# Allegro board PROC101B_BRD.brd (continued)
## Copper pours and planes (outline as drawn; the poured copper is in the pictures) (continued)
DGND on BOTTOM (solid shape): 53.45,39.36 53.54,39.31 53.54,39.22 53.52,38.81 53.8,38.51 53.86,38.43 53.83,38.35 53.77,38.26 53.72,38.16 53.64,38.09 53.54,38.14 52.81,38.32 52.63,37.58 52.63,37.53 52.59,37.5 52.48,37.5 52.47,37.55 51.76,37.75 52.06,37.07 52.09,37.07 52.14,37.02 52.1,36.97 52.09,36.97 51.85,36.36 52.49,36.3 52.83,36.3 53.04,36.1 53.04,35.37 51.92,35.37 51.92,35.34 51.86,35.34 51.5,35.2 51.43,34.82 51.41,34.73 51.33,34.69 51.25,34.69 51.23,34.7 50.99,34.82 50.73,34.75 50.62,34.75 50.57,34.84 50.57,36.72 53.22,39.36
DGND on BOTTOM (solid shape): outline of 82 points within 82.24,50.35 89.12,63.35
DGND on BOTTOM (solid shape): outline of 208 points within 36.22,114.53 44.73,125.41
DGND on BOTTOM (solid shape): outline of 202 points within 76.78,67.46 83.73,72.29
DGND on BOTTOM (solid shape): 18.78,33.55 18.87,33.5 19.27,33.07 19.85,32.94 19.93,32.91 19.96,32.83 19.95,32.7 19.96,32.57 19.93,32.49 19.85,32.46 19.27,32.33 18.87,31.9 18.78,31.85 18.69,31.9 17.05,32.16 17.35,30.53 17.41,30.44 17.45,30.35 17.47,30.32 17.47,30.25 17.4,30.25 16.55,30.44 15.87,29.9 15.78,29.85 15.69,29.9 15.33,30.3 14.82,30.47 14.73,30.53 14.75,30.64 15.04,30.93 15.04,32.19 15.23,32.38 15.58,32.38 15.9,32.69 15.91,32.69 16.02,32.76 16.1,32.85 16.14,32.94 16.2,33.03 16.48,33.22 16.69,33.5 16.78,33.55 17.78,32.93
DGND on BOTTOM (solid shape): 29.83,89.66 32.68,89.66 34.14,88.2 35.14,88.2 35.27,88.11 35.43,88.08 35.45,88.07 35.51,88.01 35.51,87.62 34.79,87.62 34.28,87.69 34.12,87.2 34.11,87.11 34.02,87.06 31.62,87.06 31.54,87.1 31.52,87.18 31.11,87.66 30.71,87.18 30.69,87.1 30.61,87.06 26.83,87.06 25.36,88.53 25.33,88.64 25.42,88.71 25.59,88.75 25.72,88.85 25.83,88.88 25.9,88.79 25.9,88.2 27.06,88.2 27.06,89.47 28.07,89.47 28.07,89.59 28.09,89.66 28.17,89.69 28.56,90.1 28.17,90.5 28.09,90.53 28.07,90.6 28.07,90.72 25.92,90.72 25.92,90.37 25.66,90.37 25,90.01 25.73,89.82 25.92,89.82 25.92,89.45 25.9,89.45 25.9,89.44 25.83,89.34 25.72,89.37 25.28,89.5 25,89.13 24.93,89.04 24.82,89.06 23.1,90.79 23.08,90.9 23.17,90.96 28.54,90.96
DGND on BOTTOM (solid shape): 129.87,24.76 129.95,24.72 129.97,24.63 129.96,24.58 129.96,24.53 129.93,24.46 129.85,24.43 129.73,24.43 129.73,22.55 129.85,22.55 129.93,22.52 129.96,22.45 130.36,22.04 130.77,22.45 130.8,22.52 130.87,22.55 131,22.55 131,23.21 131.22,23.21 131.3,23.14 131.3,21.08 130.42,20.21 127.95,20.21 126.56,18.82 125.72,18.82 125.72,19.12 124.47,19.12 124.47,18.82 124.19,18.82 124.19,19.12 122.95,19.12 122.95,18.82 122.68,18.82 122.63,18.77 122.58,18.8 122.42,18.8 122.33,18.85 122.33,18.95 122.34,19.31 122.06,19.54 121.98,19.61 122.01,19.71 124.26,21.96 124.28,21.96 124.65,22.23 124.54,22.67 124.51,22.79 124.61,22.85 125.78,22.85 125.88,22.79 125.86,22.69 126.17,22.02 126.48,22.69 126.47,22.79 126.56,22.85 127.34,22.85 127.51,22.74 127.71,22.73 127.79,22.71 127.83,22.63 127.83,22.55 127.95,22.55 128.03,22.52 128.06,22.45 128.46,22.04 128.87,22.45 128.9,22.52 128.97,22.55 129.1,22.55 129.1,24.25 129.27,24.25 129.78,24.76
DGND on BOTTOM (solid shape): 137.3,54.31 137.36,54.41 137.48,54.37 137.73,54.22 138.02,54.29 138.03,54.29 138.12,54.29 138.12,54 139.1,54 139.1,52.73 139.17,52.73 139.25,52.7 139.28,52.63 139.3,52.48 139.37,52.35 139.39,52.26 139.32,52.19 139.08,51.68 139.58,51.42 139.67,51.41 139.71,51.33 139.71,51.23 140.96,51.23 140.96,52.4 140.89,52.4 140.84,52.43 140.85,52.48 140.99,52.62 141.76,52.62 141.76,51.42 141.89,51.42 141.89,50.09 141.67,49.87 141.64,49.89 141.26,49.86 141.06,49.54 141.03,49.47 140.96,49.44 139.74,49.44 139.64,49.51 139.68,49.62 139.81,50.08 139.41,50.35 139.34,50.38 139.31,50.45 139.31,50.53 138.06,50.53 138.06,50.3 138,50.2 137.89,50.22 137.78,50.33 137.01,50.33 136.93,50.37 136.91,50.46 136.93,50.56 136.92,50.67 136.94,50.75 137.02,50.79 137.44,51.19 137.04,51.6 137.02,51.6 136.99,51.63 136.79,51.63 136.79,51.76 135.57,51.76 135.57,51.37 135.19,51.37 135.19,52.55 135.57,52.55 135.57,52.15 136.79,52.15 136.79,52.28 136.86,52.28 137.17,52.59 137.18,52.59 137.44,52.93 137.25,53.32 137.21,53.39 137.24,53.47 137.3,53.53
DGND on BOTTOM (solid shape): 45.03,120.02 47.81,120.02 47.81,119.42 47.78,119.35 47.71,119.32 47.34,118.91 47.71,118.51 47.78,118.48 47.81,118.41 47.81,117.52 47.78,117.45 47.71,117.41 47.34,117.01 47.71,116.6 47.78,116.57 47.81,116.5 47.81,115.87 50.12,115.87 50.12,116.12 54.4,116.12 54.6,116.32 54.81,116.32 54.89,116.27 54.89,116.17 55.24,115.56 55.6,116.17 55.6,116.27 55.68,116.32 55.89,116.32 56.37,115.85 56.39,115.76 56.34,115.69 56.33,114.98 56.94,115.33 56.97,115.41 57.04,115.44 59.36,115.44 59.45,115.37 59.42,115.26 59.3,115.07 59.3,114.85 59.28,114.76 59.2,114.72 58.05,114.72 57.29,113.96 56.97,113.96 56.89,114.01 56.89,114.11 56.54,114.72 56.18,114.11 56.18,114.01 56.1,113.96 55.61,113.96 54.47,115.1 46.25,115.1 45.06,116.29 45.06,117.6 44.68,117.98 44.12,117.98 44.12,118.33 44.17,118.41 44.27,118.42 44.84,118.7 44.45,119.19 44.43,119.19 44.34,119.28 44.12,119.28 44.12,119.9 44.17,119.99 44.27,119.99 44.52,119.96 44.75,120.08 44.97,120.08
DGND on BOTTOM (solid shape): outline of 90 points within 93.22,85.82 95.3,100.3
DGND on BOTTOM (solid shape): outline of 321 points within 67.53,35.26 88.08,43.75
DGND on BOTTOM (solid shape): outline of 308 points within 98.19,76.44 102.85,81.9
DGND on BOTTOM (solid shape): outline of 384 points within 91.52,67.84 94,73.66
DGND on BOTTOM (solid shape): outline of 98 points within 78.02,38.24 94.39,56.69
DGND on BOTTOM (solid shape): outline of 403 points within 94.15,70.68 100.35,73.99
DGND on BOTTOM (solid shape): outline of 412 points within 97.56,82.16 100.22,86.04
DGND on BOTTOM (solid shape): outline of 147 points within 69.09,63.03 75.49,74.32
DGND on BOTTOM (solid shape): outline of 126 points within 111.69,64.81 120.65,89.79
DGND on BOTTOM (solid shape): outline of 755 points within 85.34,66.15 89.71,74.18
DGND on BOTTOM (solid shape): outline of 855 points within 36.22,86.57 51.24,106.22
DGND on BOTTOM (solid shape): outline of 2692 points within 41.16,56.74 73.34,87.79
DGND on BOTTOM (solid shape): outline of 9214 points within 1.02,87.56 89.97,132.98
DGND on BOTTOM (solid shape): outline of 50199 points within 1.02,8.02 176.78,132.98
DGND on TOP: 140.61,88.7 140.61,132.97 176.78,132.97 176.78,88.7 171.09,88.7 170.99,88.6 170.99,81.1 167.06,81.1 167.06,78.1 165.84,76.88 164.29,76.88 164.29,84.38 157.89,84.38 157.89,76.88 155.56,76.88 154.81,77.62 154.81,81.14 151.23,81.14 151.23,77.44 150.16,76.38 146.96,76.38 146.96,88.49 146.76,88.7
DGND on TOP: 97.33,63.96 97.33,54.79 125.6,54.79 125.6,63.96 ; 5 cut-outs
DGND on TOP: 130.63,49.12 130.63,70.41 148.13,70.41 148.13,61.21 143.33,56.41 137.92,56.41 ; 1 cut-out
DGND on TOP: 106.86,33.1 115.32,33.1 115.24,33.17 115.24,40.72 112.6,43.36 112.6,46.81 111.81,46.81 109.07,44.07 109.07,38.79 106.53,36.25 106.53,33.43
DGND on TOP: 63.12,33.68 63.12,44.75 76.25,44.75 76.35,44.86 76.35,46.2 85.55,46.2 86.03,45.72 86.03,44.75 86.28,44.75 86.28,33.68 ; 2 cut-outs
DGND on TOP: 132.31,88.19 132.31,84.4 131.8,83.9 131.8,82.98 131.27,82.45 131.27,81.69 130.81,81.23 130.81,76.71 131.11,76.4 133.53,76.4 133.93,76 136.65,76 136.65,79.58 138.05,79.58 138.05,88.19
DGND on TOP: 115.19,84.2 115.19,62.87 126.26,62.87 126.26,84.2 ; 4 cut-outs
DGND on TOP: 71.48,79.32 74.17,79.32 74.19,79.3 75.62,79.3 75.97,79.65 77.14,79.65 78.59,78.21 78.59,78.18 79.3,77.47 81.58,77.47 81.64,77.42 81.64,76.99 81.23,76.58 76.17,76.58 75.95,76.81 75.95,77.55 75.77,77.72 72.54,77.72 71.48,78.79
DGND on TOP: 94.31,50.8 97.79,50.8 98.17,50.42 98.17,48.51 100.97,45.72 106.55,45.72 106.55,46.05 113.16,52.65 116.23,52.65 117.73,54.15 126.64,54.15 127.25,53.54 127.25,47.73 126.82,47.29 123.6,47.29 122.28,48.62 112.5,48.62 108.53,44.65 108.53,39.78 102.51,33.76 93.37,33.76 90.63,31.01 90.37,31.01 90.02,31.37 89.15,31.37 86.77,33.76 86.77,41.81 91.62,46.66 93.07,46.66 94.31,47.9 ; 10 cut-outs
DGND on TOP: 104.72,68.17 104.72,69.11 102.21,69.11 102.21,76.07 103.58,76.07 103.58,78.44 110.85,78.44 110.85,75.23 106.05,75.23 106.05,69.7 109.02,69.7 109.02,68.17 ; 1 cut-out
DGND on BOTTOM: 78.99,120.45 78.99,117.17 80.75,117.17 80.75,120.45
DGND on BOTTOM: 142.82,106.3 142.82,103.99 144.93,103.99 144.93,106.3
DGND on BOTTOM: 97.92,119.38 97.92,116.74 97.62,116.44 97.62,115.21 100.76,115.21 100.76,119.38
DGND on BOTTOM: 76.73,79.81 76.73,75.09 79.45,75.09 79.45,79.81
DGND on BOTTOM: 142.9,113.48 142.9,116.99 141.43,116.99 141.43,119.1 144.83,119.1 144.83,118.34 144.63,118.14 144.63,113.48
DGND on BOTTOM: 78.26,97.87 81.31,97.87 81.31,107.95 79.98,107.95 79.98,110.41 79.86,110.54 76.76,110.54 78.26,109.04
DGND on BOTTOM: 92.11,132.69 92.11,130.3 94.67,130.3 94.67,132.69
DGND on BOTTOM: 140.41,99.64 142.88,99.64 143.31,99.21 145.97,99.21 146.02,99.26 146.02,102.18 148.11,102.18 148.23,102.06 148.23,97.56 147.35,96.67 140.94,96.67 140.36,97.26 140.36,99.59
DGND on BOTTOM: 73.25,115.01 73.25,112.57 75.49,112.57 75.49,115.01
DGND on BOTTOM: 92.2,127.43 92.2,125.58 93.83,125.58 93.83,127.43
DGND on BOTTOM: 53.31,26.54 53.31,21.77 56.08,21.77 56.08,26.54
DGND on BOTTOM: 48.67,56.52 48.67,51.13 50.77,51.13 50.77,53.31 50.8,53.34 52.32,53.34 52.37,53.39 52.37,56.52
DGND on BOTTOM: 83.9,12.52 83.9,8.74 87.1,8.74 87.1,12.52
DGND on BOTTOM: 79.2,18.08 79.2,15.27 81.92,15.27 81.92,18.08
DGND on BOTTOM: 23.37,59.96 19.56,59.96 19.43,60.09 19.43,63.01 23.5,63.01 23.5,60.09
DGND on BOTTOM: 59.82,12.52 59.82,8.74 63.27,8.74 63.27,12.52
DGND on BOTTOM: 14.61,23.93 14.61,21.62 17.88,21.62 17.88,23.93
DGND on BOTTOM: 29.11,116.54 29.11,115.37 29.69,114.78 29.69,113.41 32.79,113.41 32.79,116.54
DGND on BOTTOM: 169.85,108.8 169.85,105.79 176.71,105.79 176.71,108.8
DGND on BOTTOM: 44.65,91.87 44.65,90.32 46.84,90.32 46.84,91.87
DGND on BOTTOM: 43.79,97.08 43.79,94.56 45.77,94.56 45.77,97.08
DGND on L02_GND1: 1.02,8.02 1.02,47.69 1.02,47.69 1.02,50.41 1.68,50.41 2.54,50.77 2.9,51.63 2.9,52.08 2.54,52.94 1.68,53.29 1.02,53.29 1.02,55.16 1.68,55.16 2.54,55.52 2.9,56.38 2.9,56.83 2.54,57.69 1.68,58.04 1.02,58.04 1.02,60.87 1.02,60.87 1.02,132.98 9.02,132.98 9.02,130.95 9.27,130.7 10.89,130.7 12.32,129.27 12.32,128.54 11.68,127.9 11.68,124.98 13.72,124.98 13.72,128.02 13.08,128.65 13.08,129.29 14.36,130.57 15.88,130.57 16.51,131.21 16.51,132.98 18.67,132.98 18.67,130.57 20.95,130.57 22.23,129.3 22.23,128.79 21.59,128.16 21.59,124.98 23.62,124.98 23.62,128.41 26.92,131.71 26.92,132.98 176.78,132.98 176.78,8.02 ; 7 cut-outs
DGND on L04_GND2: 1.02,8.02 1.02,47.31 1.02,47.31 1.02,50.41 1.68,50.41 2.54,50.77 2.9,51.63 2.9,52.08 2.54,52.94 1.68,53.29 1.02,53.29 1.02,55.16 1.68,55.16 2.54,55.52 2.9,56.38 2.9,56.83 2.54,57.69 1.68,58.04 1.02,58.04 1.02,60.52 1.02,60.52 1.02,132.98 176.78,132.98 176.78,8.02 ; 6 cut-outs
DGND on L07_GND3: 1.02,8.02 1.02,46.95 1.02,46.95 1.02,50.41 1.68,50.41 2.54,50.77 2.9,51.63 2.9,52.08 2.54,52.94 1.68,53.29 1.02,53.29 1.02,55.16 1.68,55.16 2.54,55.52 2.9,56.38 2.9,56.83 2.54,57.69 1.68,58.04 1.02,58.04 1.02,60.39 1.02,60.39 1.02,132.98 176.78,132.98 176.78,8.02 ; 6 cut-outs
DGND on L09_GND4: 1.02,8.02 1.02,49.01 1.02,49.01 1.02,50.41 1.68,50.41 2.54,50.77 2.9,51.63 2.9,52.08 2.54,52.94 1.68,53.29 1.02,53.29 1.02,55.16 1.68,55.16 2.54,55.52 2.9,56.38 2.9,56.83 2.54,57.69 1.68,58.04 1.02,58.04 1.02,60.34 1.02,60.34 1.02,132.98 176.78,132.98 176.78,8.02 ; 6 cut-outs
GNDUSB on TOP: 168.23,35.45 168.23,38.94 174.69,38.94 174.94,39.2 174.94,42.18 174.69,42.43 173.04,42.43 173.04,46.5 177.35,46.5 177.35,35.45
VCC1V2_DDR on TOP: 98,119.81 98,126.22 101.85,126.22 101.85,119.81
VCC1V2_DDR on TOP: 87.36,115.06 87.36,119.63 92.46,119.63 92.46,115.06
VCC1V2_DDR on BOTTOM: 87.88,119.78 92.99,119.78 92.99,115.08 87.88,115.08
VCC1V2_DDR on L08_SIG2: 87.76,115.57 93.85,115.57 93.85,118.75 94.87,119.76 102.23,119.76 102.23,124.01 93.53,124.01 87.76,118.24
VCC1V8 on TOP: 53.99,64.35 53.99,61.93 56.13,61.93 56.13,64.35
VCC1V8 on TOP: 95.85,37.99 95.85,36.29 102.11,36.29 102.11,37.99
VCC1V8 on TOP: 132.08,116.02 139.56,116.02 139.56,107.34 132.08,107.34
VCC1V8 on TOP: 46.36,63.13 46.36,61.28 47.48,60.15 48.75,60.15 48.75,63.13
VCC1V8 on TOP: 113.06,46.85 113.06,45.61 121.74,45.61 121.74,46.85
VCC1V8 on BOTTOM: 132.08,107.34 132.08,112.03 134.49,112.03 134.49,116.62 139.59,116.62 139.88,116.33 142.37,116.33 142.37,110.12 139.59,107.35 137.19,107.35 137.19,107.34
VCC1V8 on L03_SIG1: 49.23,65.38 54.46,65.38 56.67,63.17 56.67,60.88 55.85,60.07 48.41,60.07 47.78,60.71 47.78,63.93
VCC1V8 on L06_PWR2: 127.52,36.52 118.45,27.45 94.61,27.45 90.42,31.64 90.42,49.8 90.55,49.93 119.28,49.93 133.74,64.38 137.28,64.38 147.57,74.68 147.57,92.01 131.95,107.63 131.95,110.18 130.11,112.03 126.55,112.03 122.98,115.6 95.78,115.6 91.52,119.86 75.55,119.86 74.11,118.42 74.11,95.19 67.96,95.19 67.96,109.22 61.85,109.22 61.85,111.84 67.87,111.84 67.96,111.93 67.96,122.07 70.46,124.57 81.14,124.57 82.51,123.2 84.74,123.2 86.11,124.57 95.63,124.57 98.44,121.77 129.96,121.77 131.55,120.18 145.6,120.18 156.46,109.32 156.46,65.46 144.82,53.81 137.79,53.81 137.79,50.81 136.91,49.93 135.89,49.93 134.62,51.2 132.46,51.2 127.52,46.25
VCC1V8_HSE on TOP: 74.24,124.81 70.61,124.81 70.61,122.44 74.55,122.44 74.55,124.5
VCC1V8_HSE on BOTTOM: 70.36,122.44 70.36,129.14 71.91,130.7 74.55,130.7 74.55,125.11 74.55,125.11 74.55,123.46 73.53,122.44
VCC3V3_IO_HSE on TOP: 38.69,121.76 38.69,124.02 38.39,124.32 37.94,124.32 37.88,124.37 37.88,126 41.53,126 41.53,121.76
VCC3V3_IO_HSE on BOTTOM: 38.44,124.98 38.44,120.42 41.27,120.42 41.27,124.98
VCC3V3_PREREG on TOP: 97.28,119.11 95.24,119.11 94.11,117.98 94.11,115.25 97.13,115.25 97.13,117.61 96.9,117.84 96.9,118.6 97.03,118.73 97.28,118.73
VCC3V3_PREREG on TOP: 149.79,96.95 158.01,96.95 158.01,101.94 149.32,101.94 149.32,97.42
VCC3V3_PREREG on TOP: 136.6,57.5 136.6,59.79 139.51,59.79 139.51,57.84 139.17,57.5
VCC3V3_PREREG on TOP: 131.09,75.72 132.86,75.72 132.86,73.31 134.01,73.31 134.01,71.18 131.09,71.18
VCC3V3_PREREG on TOP: 156.19,102.38 156.19,104.79 159.26,104.79 159.64,104.41 159.64,102.76 159.26,102.38
VCC3V3_PREREG on BOTTOM: 142.11,102.5 141.6,102.5 140.39,101.28 140.39,100.05 142.73,100.05 142.73,101.88
VCC3V3_PREREG on BOTTOM: 144.91,122.82 141.22,122.82 141.22,119.9 141.48,119.65 144.78,119.65 144.91,119.78
VCC3V3_PREREG on L05_PWR1: 132.73,56.64 131.95,57.42 131.95,66.57 135.62,66.57 136.5,67.45 136.5,70.9 136.14,71.26 131.17,71.26 128.6,73.83 128.6,94.22 129.79,95.41 134.72,95.41 143.26,103.95 143.26,113.3 135.76,120.79 98.04,120.79 97.93,120.91 97.93,115.33 97.16,114.55 93.34,114.55 92.84,115.06 92.84,121.93 98.3,127.4 141,127.4 160.53,107.87 160.53,101.97 151,92.45 139.76,92.45 136.84,89.53 136.84,81.49 143.25,75.08 143.25,66.93 140.84,64.53 140.84,57.29 140.19,56.64 ; 1 cut-out
VCC3V3_TA on TOP: 72.39,21.1 72.39,16.77 75.16,14 84.09,14 84.71,14.62 84.71,17.92 84.45,18.18 77.95,18.18 75.03,21.1
VCC3V3_TA on BOTTOM: 57.66,21.1 50.14,21.1 50.14,13.6 55.37,13.6 55.37,18.3 56.82,19.75 57.51,19.75 57.66,19.89
VCC3V3_TA on BOTTOM: 82.27,17.82 82.27,13.17 84.96,13.17 84.96,17.82
VCC3V3_TA on BOTTOM: 66.52,20.87 66.52,19.65 72.95,19.65 72.95,20.87
VCC3V3_TA on L05_PWR1: 50.51,14.4 50.51,16.65 57.24,23.38 66.42,23.38 68.33,21.48 68.33,18.3 63.88,13.86 51.05,13.86
VCC3V3_TA on L06_PWR2: 64.01,21.86 64.01,51.37 69.72,57.09 69.72,65.04 70.62,65.94 72.26,65.94 73.15,65.04 73.15,61.36 73.77,60.73 79.97,60.73 86.71,53.99 109.73,53.99 109.98,53.74 109.98,42.56 112.19,40.35 112.19,38.4 111.65,37.86 104.9,37.86 103.98,38.78 103.98,40.25 106.17,42.43 106.17,50.13 105.49,50.81 73.7,50.81 72.71,49.82 72.71,26.11 74.55,24.27 96.9,24.27 98.55,22.62 98.55,18.94 66.93,18.94
VCC3V3_XDS on TOP: 167.39,11.44 167.39,10.56 167.26,10.43 163.58,10.43 163.58,12.08 164.72,12.08 165.35,11.44
VCC3V3_XDS on L05_PWR1: 139.04,23.76 133.48,23.76 131.95,25.29 131.95,28.84 135.64,32.53 154.56,32.53 159.51,27.57 162.69,27.57 165.93,24.33 165.93,10.29 163.91,8.27 150.61,8.27 140.46,18.42 140.46,22.34
VCC3V3_XDS on L08_SIG2: 140.51,17.04 125.96,31.6 125.96,46.13 122.89,49.2 122.89,56.16 136.63,56.16 138.86,53.92 138.86,39.12 142.85,35.13 153.82,35.13 158.24,30.71 158.24,22.38 152.91,17.04
VCC_1V8_FT4232 on TOP: 132.24,46.75 132.24,37.83 135.13,34.94 146.43,34.94 149.35,37.86 149.35,45.35 148.84,45.86 146.43,45.86 144.15,43.58 144.15,41.13 142.12,39.11 135.8,39.11 134.49,40.42 134.49,46.24 133.99,46.75
VCC_3V3_FT4232 on L06_PWR2: 128.27,46.75 134.37,52.85 144.4,52.85 144.4,48.91 143.51,48.02 138.94,48.02 134.24,43.32 134.24,37.35 135.38,36.21 145.67,36.21 147.45,37.99 147.45,43.58 156.21,43.58 156.21,41.04 147.4,32.23 141.74,32.23 136.7,27.19 128.4,27.19 125.48,30.11 125.48,33.15 128.27,35.94
VCC_3V3_MIPI on BOTTOM: 58.55,53.48 58.55,52.16 61.85,52.16 61.85,53.48
VCC_3V3_MIPI on L08_SIG2: 59.69,52.21 59.69,53.23 62.1,53.23 62.1,52.21
VCC_3V3_SYS on TOP: 32.51,116.85 32.51,118.25 31.74,119.02 28.65,119.02 28.65,117.01 31.02,117.01 31.24,117.24 32,117.24 32.13,117.11 32.13,116.85
VCC_3V3_SYS on TOP: 119.75,62.53 119.95,62.33 119.95,60.85 114.71,60.85 114.71,61.75 116.1,61.75 116.89,62.53
VCC_3V3_SYS on TOP: 20.75,45.99 20.75,43.7 26.04,43.7 26.04,45.99
VCC_3V3_SYS on TOP: 138.55,88.15 138.56,88.15 138.56,93.02 142.04,93.02 142.04,88.79 146.25,88.79 146.25,77.42 138.98,77.42 138.55,77.85
VCC_3V3_SYS on TOP: 19.56,59.7 19.56,58.31 20.33,57.54 23.42,57.54 23.42,59.63 21.14,59.63 20.83,59.32 20.07,59.32 19.94,59.45 19.94,59.7
VCC_3V3_SYS on BOTTOM: 48.5,92.8 47.31,92.8 47.31,90.57 47.56,90.31 48.96,90.31 49.38,90.73 49.38,91.92
VCC_3V3_SYS on BOTTOM: 43.58,45.35 43.58,46.88 52.84,46.88 52.84,45.35
VCC_3V3_SYS on BOTTOM: 138.56,93.28 141.55,93.28 143.62,91.21 145.37,91.21 145.37,80.54 138.55,80.54 138.55,88.15 138.56,88.15
VCC_3V3_SYS on BOTTOM: 91.72,129.74 91.72,132.65 90.42,132.65 90.42,129.74
VCC_3V3_SYS on BOTTOM: 74.82,120.4 76.21,120.4 77.09,119.52 77.09,116.94 76.71,116.94 76.71,118.38 76.26,118.83 74.82,118.83
VCC_3V3_SYS on BOTTOM: 15.75,18.68 16.26,18.68 17.48,19.9 17.48,21.21 15.24,21.21 14.99,20.96 14.99,19.45
VCC_3V3_SYS on BOTTOM: 75.82,112.22 76.71,112.22 76.71,115.46 75.82,115.46
VCC_3V3_SYS on L05_PWR1: 1.35,53.3 1.02,53.3 1.02,55.16 1.68,55.16 2.54,55.52 2.9,56.38 2.9,56.83 2.54,57.69 1.68,58.04 1.02,58.04 1.27,59.12 1.27,132.98 175.81,132.98 175.81,8.02 1.27,8.02 1.27,47.79 1.06,47.79 1.06,50.41 1.44,50.41 1.83,50.41 2.64,50.78 2.9,51.63 2.9,52.08 2.54,52.94 1.68,53.29 ; 7 cut-outs
VCC_3V3_SYS on L06_PWR2: 1.27,8.02 1.27,132.98 177.04,132.98 177.04,8.02 ; 38 cut-outs
VCC_5V0 on TOP: 171.63,87.52 171.63,79.83 176.73,79.83 176.73,88.14 172.26,88.14
VCC_5V0 on TOP: 81.72,125.48 81.72,122.4 84.79,122.4 84.79,125.48
VCC_5V0 on TOP: 34.87,48.53 33.48,48.53 33.1,48.91 33.1,51.32 33.22,51.45 34.75,51.45 35.13,51.07 35.13,48.78
VCC_5V0 on BOTTOM: 171.63,87.52 171.63,79.83 176.78,79.83 176.78,88.14 172.26,88.14
VCC_5V0 on L03_SIG1: 24.26,118.38 24.26,116.47 26.29,116.47 26.29,118.38
VCC_5V0 on L03_SIG1: 33.81,49.47 33.81,51.25 35.2,51.25 35.2,49.47
VCC_5V0 on L06_PWR2: 173.01,81.29 173.01,106 158.08,120.93 132.07,120.93 130.65,122.35 98.78,122.35 95.88,125.24 85.96,125.24 84.42,123.7 82.65,123.7 81.11,125.24 34.04,125.24 28.32,119.52 28.32,112.92 16.64,112.92 16.64,126.75 22.87,132.98 174.75,132.98 176.71,131.02 176.71,81.29
VCC_5V0_HSE on TOP: 70.75,126.07 70.75,125.11 74.29,125.11 74.8,124.6 80.64,124.6 80.9,124.86 80.9,127.01 79.5,128.41 75.56,128.41 74.53,127.38 74.53,126.22 74.38,126.07
VCC_CORE on TOP: 124.16,77.54 124.16,83.58 127.41,83.58 128.05,84.21 128.05,91.99 131.97,91.99 131.97,84.71 131.32,84.05 131.32,83.26 130.81,82.75 130.81,81.89 130.32,81.41 130.32,77.54
VCC_LM5140 on TOP: 159.51,71.4 159.51,69.98 163.65,69.98 163.65,71.4
VDD1V8_CLKBUF on TOP: 61.47,111.99 61.47,109.58 57.66,109.58 57.66,111.99
VDD1V8_CLKBUF on L03_SIG1: 57.84,102.29 61.6,102.29 61.72,102.41 61.72,111.35 58.01,111.35 58.01,103.07 57.84,102.9
VDD3V3_CLKBUF on L05_PWR1: 52.83,105.55 52.83,109.36 54.48,111.01 67.31,111.01 67.65,110.67 67.65,109.02 68.58,108.09 73.91,108.09 75.56,106.44 75.56,103.52 74.8,102.76 68.71,102.76 67.82,101.87 67.82,95.39 65.66,93.23 62.87,93.23 59.69,96.41 59.69,99.46 54.74,104.41 53.98,104.41
VDD_0V85 on TOP: 154.55,106.31 153.53,107.33 150.63,107.33 150.63,109.21 150.63,109.21 150.63,114.31 155.45,114.31 155.45,106.44 155.32,106.31
VDD_0V85 on BOTTOM: 155.32,116.34 155.32,107.57 150.79,107.57 150.79,116.34
VDD_1V0 on BOTTOM: 44.34,92.44 45.17,92.44 45.17,94.17 41.2,94.17 40.89,93.87 40.89,91.58 41.15,91.33 43.23,91.33
VDD_1V0 on L05_PWR1: 34.04,101.61 34.04,104.28 36.7,106.95 39.51,106.95 39.72,106.74 39.72,104.95 42.67,102 48.64,102 49.15,101.49 49.15,99.71 48.78,99.34 44.2,99.34 43.91,99.05 43.91,91.93 43.31,91.33 41.36,91.33 41.01,91.69 41.01,93.15 41.82,93.96 41.82,97.01 38.73,100.09 35.56,100.09
VDD_1V1 on TOP: 18.86,59.9 12.45,59.9 12.45,65.47 18.86,65.47
VDD_1V1 on L06_PWR2: 13.08,66.31 13.08,59.58 15.75,56.91 43.78,56.91 49.55,62.68 49.55,86.53 47.76,88.31 40.99,88.31 35.24,82.56 34.54,82.56 34.54,81.68 35.81,81.68 35.81,66.44 34.29,66.44 34.29,65.42 35.69,65.42 35.69,62.5 29.28,62.5 25.47,66.31
VDD_2V5 on TOP: 33.21,116.14 39.62,116.14 39.62,111.09 33.21,111.09
VDD_2V5 on L06_PWR2: 29.46,63.26 35.17,63.26 35.17,64.54 34.92,64.78 33.4,64.78 33.27,64.91 33.27,66.94 33.53,67.2 34.92,67.2 35.17,67.44 35.17,80.62 34.87,80.91 33.66,80.91 33.4,81.17 33.4,83.2 33.53,83.33 34.92,83.33 35.17,83.57 35.17,101.41 39.5,105.75 39.5,113.26 38.7,114.06 32.76,114.06 27.3,108.6 27.3,65.42
VDD_2V8 on BOTTOM: 20.09,13.29 20.09,18.81 16.51,18.81 15.49,17.79 15.49,13.29
VDD_CORE on TOP: 121.51,84.11 121.51,90.57 119.06,90.57 119.06,99.31 124.97,99.31 124.97,91.45 127.38,91.45 127.38,84.11
VDD_CORE on BOTTOM: 103.63,81.03 100.6,81.03 100.6,86.49 103.63,86.49
VDD_CORE on L05_PWR1: 111.3,83.76 107.44,79.9 107.44,76.98 106.52,76.06 93.82,76.06 93.38,75.62 92.84,75.62 92.84,76.25 92.64,76.45 91.85,76.45 91.69,76.3 91.69,75.62 91.06,75.62 91.06,76.34 92.08,77.36 92.08,78.88 91.82,79.14 90.42,79.14 90.04,78.75 90.04,77.36 89.79,77.1 89.03,77.1 88.9,77.23 88.9,77.99 87.76,79.14 87.76,85.1 90.64,87.99 97.95,87.99 98.46,88.5 107.24,97.55 125.42,97.55 127.64,95.34 127.64,85.23 126.36,83.96 122.95,83.96 119.26,87.64 112.39,87.64 111.3,86.55 ; 1 cut-out
VDD_DDR4 on TOP: 86.91,119.78 86.91,115.05 81.9,115.05 81.9,119.78
VDD_DDR4 on BOTTOM: 97.79,92.12 99.82,92.12 99.82,86.5 97.79,86.5
VDD_DDR4 on BOTTOM: 74.8,118.19 74.8,117.04 74.89,116.96 76.55,116.96 76.55,118.19
VDD_DDR4 on L06_PWR2: 91.06,81.93 91.06,80.02 91.44,79.64 93.6,79.64 94.36,80.41 96.26,80.41 98.17,80.28 104.01,86.12 104.01,105.99 90.89,119.12 76.42,119.12 75.4,118.11 75.4,101.91 87.5,89.81 87.5,85.49
VDD_DLL_MMC0 on BOTTOM: 115.82,70.5 115.82,75.58 113.18,75.58 113.18,71.63 112.62,71.07 112.62,70.5
VDD_MMC1 on TOP: 113.06,62.64 113.06,59.83 110.14,59.83 108.97,61.01 108.97,62.66 113.03,62.66
VDD_MMC1 on L03_SIG1: 103.96,73.07 103.96,72.63 106.1,70.5 106.1,67.25 108.64,64.71 108.64,62.22 109.29,61.56 111.63,61.56 111.63,68.09 106.65,73.07
VDD_MMC1 on L06_PWR2: 39.6,22.27 39.6,19.65 42.32,19.65 42.32,22.27
VDD_MMC1 on L06_PWR2: 108.97,62.68 108.97,61.24 110.28,61.24 110.28,62.68
VDDA1V8 on TOP: 126.24,63.58 126.24,67.06 126.25,67.07 130.94,67.07 130.94,61.96 130.93,61.96 130.93,61.01 132.62,59.33 134.36,59.33 135,58.69 135,57.55 132.72,57.55 132.33,57.16 130.43,57.16 130.43,59.39
VDDA1V8 on BOTTOM: 128.81,57.93 126.24,60.5 126.24,67.06 126.25,67.07 130.94,67.07 130.94,61.96 130.93,61.96 130.93,60.99 132.1,59.82 132.1,58.34 131.7,57.93
VDDA_1V8 on TOP: 130.81,68.05 126.21,68.05 126.21,72.63 130.81,72.63
VDDA_1V8 on TOP: 90.3,58.31 90.3,55.01 91.69,55.01 91.69,58.31
VDDA_1V8 on TOP: 109.22,68.09 109.22,69.99 111.12,69.99 111.12,77.87 111.89,77.87 112.27,78.25 112.27,80.66 108.71,80.66 108.71,83.58 109.47,83.58 109.47,85.1 112.01,85.1 112.01,82.69 113.86,80.84 113.86,68.09
VDDA_1V8 on BOTTOM: 130.82,68.05 126.21,68.05 126.21,73.06 130.82,73.06
VDDA_1V8 on BOTTOM: 108.05,80.51 108.05,83.59 110.59,83.59 110.62,83.57 110.62,81.38 109.74,80.51
VDDA_1V8 on BOTTOM: 110.72,71.13 112.14,71.13 112.14,68.47 111.89,68.21 108.71,68.21 108.58,68.34 108.58,69.86 108.84,70.12 110.72,70.12
VDDA_1V8 on BOTTOM: 91.47,62.37 91.47,58.99 94.31,58.99 94.31,62.37
VDDA_1V8 on L03_SIG1: 94.7,78.3 94.91,78.09 94.91,75.7 94.07,74.86 91.4,74.86 90.3,75.97 90.3,78.3
VDDA_1V8 on L06_PWR2: 89.46,54.75 75.06,69.15 75.06,78.5 71.02,82.54 71.02,84.9 71.4,85.28 76.4,85.28 79.91,81.78 79.91,75.88 81.02,74.77 81.02,70.98 89.61,62.39 92.53,62.39 96.17,66.03 104.37,66.03 109.73,71.39 133.86,71.39 133.86,67.58 131.95,65.67 112.43,65.67 101.51,54.75 ; 3 cut-outs
VDDA_1V8 on L08_SIG2: 89.42,74.09 89.42,77.53 90.18,78.29 94.75,78.29 95.28,77.77 95.28,74.74 94.19,73.65 89.86,73.65
VDDA_1V8_MCU on TOP: 106.43,72.53 110.45,72.53 110.45,69.86 107.44,69.86 107.19,69.61 106.43,69.61
VDDA_1V8_MCU on BOTTOM: 108.66,72.66 110.24,72.66 110.24,70.66 108.66,70.66
VDDA_1V8_MCU on L05_PWR1: 92.03,76.09 92.03,75.73 91.59,75.3 91.59,74.36 91.86,74.09 92.04,74.09 93.91,72.22 98.84,72.22 100.31,70.75 110.11,70.75 110.24,70.88 110.24,75.66 93.85,75.66 93.52,75.33 92.91,75.33 92.5,75.74 92.5,76.09 92.44,76.15 92.08,76.15 ; 1 cut-out
VDDA_1V8_SERDES on TOP: 88.27,58.94 88.27,65.42 92.33,65.42 92.33,58.94
VDDA_1V8_SERDES on L05_PWR1: 86.04,66.85 86.04,64.55 86.4,64.19 90.82,64.19 91.12,64.49 91.12,65.86 87.76,69.23 87.76,74.43 87.14,75.05 80.57,75.05 80.57,67.77 80.58,67.77 85.12,67.77
VDDA_1V8_USB0 on BOTTOM: 88.2,62.35 88.2,65.63 92.36,65.63 92.36,62.75 91.06,62.75 91.06,59.04 89.43,59.04 89.43,62.35
VDDA_1V8_USB0 on L06_PWR2: 85.89,73.93 87.63,73.93 87.88,73.67 87.88,69.23 90.68,66.44 92.58,66.44 92.96,66.05 92.96,63.64 92.33,63.01 89.71,63.01 85.27,67.44 85.27,73.32
VDDA_ADC on BOTTOM: 109.35,74.82 109.35,72.93 110.62,72.93 110.62,71.64 112.24,71.64 112.4,71.81 112.4,74.82
VDDA_CORE on TOP: 113.03,100.68 118.56,100.68 118.56,94.4 116.59,94.4 116.59,96.56 115.82,97.33 113.03,97.33
VDDA_CORE on BOTTOM: 116.2,72.03 116.2,70.1 118.69,70.1 118.69,71.58 118.06,71.58 117.6,72.03
VDDA_CORE on BOTTOM: 69.77,77.99 69.77,81.76 72.26,81.76 72.26,77.99
VDDA_CORE on L03_SIG1: 117.22,70.88 117.22,69.74 118.87,69.74 118.87,70.88
VDDA_CORE on L03_SIG1: 113.28,100.98 113.28,99.84 115.57,99.84 115.57,100.98
VDDA_CORE on L05_PWR1: 113.28,100.85 113.28,99.84 115.44,99.84 115.44,100.85
VDDA_CORE on L05_PWR1: 70.41,79.34 70.41,80.23 72.19,80.23 72.19,79.34
VDDA_PLL0 on BOTTOM: 72.62,82.29 75.39,82.29 76.31,81.36 77.45,81.36 77.55,81.46 79.27,81.46 79.35,81.38 79.35,82.69 78.36,83.68 72.62,83.68
VDDA_PLL1 on BOTTOM: 103.31,78.63 109.5,78.63 109.5,80.23 103.31,80.23
VDDA_PLL2 on TOP: 105.03,87.52 105.03,85.36 106.03,85.36 106.29,85.61 111.38,85.61 111.38,87.52
VDDAR_0P85_SERDES0 on TOP: 72.9,77.48 75.69,77.48 75.69,75.71 72.9,75.71
VDDAR_0P85_SERDES0 on BOTTOM: 71.5,74.69 71.5,77.36 72.75,77.36 72.75,79.19 74.14,79.19 74.14,74.69
VDDAR_0P85_SERDES0 on L05_PWR1: 73.37,78.85 87.54,78.85 88.59,77.8 88.59,74.93 88.03,74.93 87.17,75.78 86.74,75.78 86.64,75.68 86.54,75.68 85.85,76.37 82.07,76.37 81.49,75.79 75.58,75.79 74.6,74.82 72.77,74.82 72.39,75.2 72.39,77.87
VDDAR_0P85_USB0 on BOTTOM: 72.75,81.96 72.75,80.02 74.52,80.02 74.52,74.78 76.54,74.78 76.71,74.94 76.71,75.88 76.12,76.47 76.12,80.67 74.84,81.96
VDDAR_CORE on TOP: 113.28,96.03 113.28,90.87 119.76,90.87 119.94,91.05 119.94,93.69 119.89,93.74 116.33,93.74 116.08,93.99 116.08,95.77 115.82,96.03
VDDAR_CORE on TOP: 150.15,115.2 150.15,111.75 145.14,111.75 145.14,116.47 148.88,116.47
VDDAR_CORE on BOTTOM: 150.15,116.47 150.15,111.75 150.11,111.75 150.5,111.37 150.5,105.55 149.86,104.92 148.59,104.92 147.57,105.93 147.57,109.32 145.14,111.75 145.14,116.47
VDDAR_CORE on L03_SIG1: 123.83,116.47 150.75,116.47 150.75,112.54 147.7,109.49 142.77,109.49 130.84,97.55 120.9,97.55 116.97,93.61 116.97,91.12 112.65,91.12 112.65,96.6 123.83,107.77
VDDC_1V2 on TOP: 163.32,21.86 163.32,23.18 168.04,23.18 168.04,21.86
VDDR_CORE on TOP: 116.68,80.48 116.68,80.02 118.92,80.02 118.97,80.08 118.97,81.85 118.85,81.98 118.85,83.68 119.3,84.14 120.65,84.14 120.65,89.53 120.65,89.96 115.42,89.96 115.42,81.75
VDDR_CORE on TOP: 107.19,80.34 107.19,78.63 111.72,78.63 111.72,80.34
VDDR_CORE on L05_PWR1: 88.88,75.77 90.45,77.34 90.45,78.65 90.57,78.77 91.57,78.77 91.7,78.64 91.7,77.4 90.73,76.44 90.73,74.89 93.9,71.72 98.04,71.72 100.15,69.61 110.36,69.61 111,70.25 111,76.21 109.47,77.74 109.47,80.79 109.6,80.91 113.46,80.91 116.36,83.81 118.49,83.81 118.49,82.31 119,81.8 119,80.15 118.52,79.67 118.52,76.1 118.49,76.08 118.49,74.24 112.09,67.83 111.49,67.83 109.29,65.64 97.57,65.64 95.38,67.83 90.81,67.83 88.88,69.76
VDDR_VTT on TOP: 84.33,95.39 96.77,95.39 96.77,97.92 98.68,97.92 98.68,93.61 82.65,93.61 81.15,95.12 81.15,97.93 83.06,97.93 84.07,96.92 84.07,95.65
VDDR_VTT on BOTTOM: 77.22,118.63 77.22,117.11 77.72,117.11 77.72,117.74 78.61,118.63 78.61,120.65 80.21,122.25 80.21,123.89 77.34,123.89 77.34,118.76
VDDR_VTT on BOTTOM: 81.41,95.51 81.41,106.87 83.95,106.87 83.95,95.9 84.96,94.88 94.17,94.88 94.17,91.9 92.81,91.9 92.81,92.53 92.26,93.08 83.84,93.08
VDDR_VTT on L05_PWR1: 76.96,124.09 76.96,121.55 78.23,120.28 78.23,117.11 81.92,113.43 81.92,95.26 96.79,95.26 101.73,100.2 101.73,106.19 86.23,106.19 86.23,117.74 78.99,124.98 77.85,124.98
VDDSHV_SD_IO on BOTTOM: 90.93,74.55 91.95,74.55 91.95,73.91 92.58,73.91 92.58,73.15 91.06,73.15 91.06,69.47 91.82,68.71 91.82,67.69 93.09,67.69 93.22,67.56 93.22,66.17 90.17,66.17 90.17,73.41 90.93,74.17
VDDSHV_SD_IO on L05_PWR1: 36.64,28.21 43.69,28.21 47.75,32.27 47.75,56.15 58.43,66.83 94.73,66.83 95.63,65.93 95.63,62.24 92.49,59.09 58.77,59.09 54.1,54.43 54.1,31.26 47.5,24.65 36.84,24.65 36.4,25.09 36.4,27.97
(no net) on TOP: outline of 123 points within 1.02,8.02 176.78,132.98 ; 59 cut-outs
(no net) on BOTTOM: 1.02,8.02 1.02,49.01 1.02,49.01 1.02,50.41 1.68,50.41 2.54,50.77 2.9,51.63 2.9,52.08 2.54,52.94 1.68,53.29 1.02,53.29 1.02,55.16 1.68,55.16 2.54,55.52 2.9,56.38 2.9,56.83 2.54,57.69 1.68,58.04 1.02,58.04 1.02,60.34 1.02,60.34 1.02,132.98 176.78,132.98 176.78,8.02 ; 115 cut-outs
(no net) on L03_SIG1: outline of 138 points within 1.02,8.02 176.78,132.98 ; 138 cut-outs
(no net) on L08_SIG2: 34.04,8.02 34.03,8.02 1.02,8.02 1.02,47.69 1.02,47.69 1.02,50.41 1.68,50.41 2.54,50.77 2.9,51.63 2.9,52.08 2.54,52.94 1.68,53.29 1.02,53.29 1.02,55.16 1.68,55.16 2.54,55.52 2.9,56.38 2.9,56.83 2.54,57.69 1.68,58.04 1.02,58.04 1.02,60.87 1.02,60.87 1.02,61.94 1.02,61.94 1.02,66.84 1.02,66.84 1.02,132.98 176.78,132.98 176.78,111.39 176.78,111.39 176.78,106.82 176.78,106.82 176.78,8.02 50.31,8.02 50.31,8.02 ; 147 cut-outs
CPSW_EARTH on TOP: 2.79,90.69 1.02,92.47 1.02,110.5 1.04,110.5 1.04,111.2 10.97,111.2 11.96,110.21 11.96,104.69 10.74,103.47 10.74,95.69 12.67,93.77 15.49,93.77 15.49,91.2 14.99,90.69
CPSW_EARTH on BOTTOM: 1.76,91.73 1.02,92.47 1.02,110.59 1.4,110.97 10.95,110.97 11.94,109.98 11.94,104.67 10.74,103.48 10.74,95.58 12.57,93.75 15.09,93.75 15.09,91.03 4.45,91.03 3.75,91.73
DDR_VPP on BOTTOM: 87.38,109.49 87.38,109.97 86.33,111.02 83.39,111.02 83.39,109.35 86.6,109.35 86.74,109.49
DDR_VREFCA on BOTTOM: 78.03,115.58 78.03,112.59 79.37,112.59 79.37,115.58
FT4232_USB_VBUS on TOP: 170.88,41.92 170.88,46.24 172.28,46.24 172.28,41.92
FT4232_USB_VBUS on BOTTOM: 164.59,39.13 164.59,45.61 165.74,46.75 171.83,46.75 172.34,46.24 172.34,42.46 168.63,38.75 164.97,38.75
MAIN on TOP: 167.26,119.76 167.26,111.15 166.78,110.67 166.78,106.93 160.42,106.93 160.42,119.76
PRG_EARTH on L02_GND1, L04_GND2, L07_GND3, L09_GND4: 2.66,64.03 1.02,65.67 1.02,87.26 24.38,87.26 27.3,84.34 27.3,81.68 26.42,80.79 9.4,80.79 8.13,79.52 8.13,71.26 10.03,69.36 21.98,69.36 23.39,67.94 23.39,65.38 22.05,64.03
PRG_EARTH on L03_SIG1: 2.66,64.03 1.02,65.67 1.02,88.24 23.41,88.24 27.3,84.34 27.3,81.68 26.42,80.79 9.4,80.79 8.13,79.52 8.13,71.26 10.03,69.36 21.98,69.36 23.39,67.94 23.39,65.38 22.05,64.03
SHIELD on TOP, L02_GND1, L03_SIG1, L04_GND2, L07_GND3, L08_SIG2, L09_GND4: 168.73,110.49 168.73,114.25 173,114.25 173,121.31 172.57,121.74 168.73,121.74 168.73,124.56 176.59,124.56 176.59,110.49
SHIELD on BOTTOM: 168.73,109.34 168.73,114.25 173,114.25 173,121.31 172.57,121.74 168.73,121.74 168.73,124.56 176.59,124.56 176.59,109.34
SOC_DVDD1V8 on TOP: 106.23,74.82 109.44,74.82 109.44,73.04 106.23,73.04
SOC_DVDD1V8 on TOP, BOTTOM: 131.1,112.03 131.1,107.31 126.09,107.31 126.09,112.03
SOC_DVDD1V8 on L03_SIG1: 89.53,73.29 89.53,76.09 89.66,76.21 96.52,76.21 96.65,76.09 96.65,73.55 95.5,72.4 90.42,72.4
SOC_DVDD1V8 on L06_PWR2: 125.98,111.35 125.98,105.24 138.81,92.42 138.81,82.75 132.92,76.86 109.3,76.86 104.31,71.87 94.23,71.87 93.31,72.79 93.31,73.95 92.44,74.83 89.72,74.83 89.51,74.62 89.51,70.76 92.39,67.88 105.45,67.88 109,71.42 134.21,71.42 146.25,83.46 146.25,90.82 131.25,105.82 131.25,110.02 129.92,111.35
SOC_DVDD3V3 on TOP: 137.82,92.98 137.82,88.89 132.88,88.89 132.88,92.98
SOC_DVDD3V3 on BOTTOM: 102.83,73.27 105.53,73.27 105.53,74.86 102.83,74.86
SOC_DVDD3V3 on BOTTOM: 137.82,92.98 137.82,88.89 132.88,88.89 132.88,92.98
SOC_DVDD3V3 on L06_PWR2: 86.61,81.8 90.81,81.8 90.81,79.64 91.19,79.26 93.6,79.26 94.49,80.15 95.12,80.15 96.02,79.26 96.02,77.72 96.87,76.87 99.43,76.87 103.78,81.21 124.55,81.21 132.5,89.16 132.5,92.89 136.86,92.89 137.92,91.84 137.92,87.01 128.63,77.72 108.95,77.72 105.77,74.55 105.77,74.5 104.38,73.11 99.22,73.11 98.45,73.88 93.98,73.88 92.53,75.33 89.54,75.33 88.9,74.68 88.9,72.79 88.14,72.79 88.02,72.9 88.02,73.83 87.69,74.16 86.76,74.16 86.11,74.82 86.11,81.29
USB0_VBUS on TOP: 24.63,51.45 14.73,51.45 9.47,46.19 6.07,46.19 5.16,47.11 5.16,53.3 9.52,53.3 10.97,54.75 24.63,54.75
USB1_SHIELD on TOP: 1.02,49.04 1.02,50.41 1.68,50.41 2.54,50.77 2.9,51.63 2.9,52.08 2.54,52.94 1.68,53.29 1.02,53.29 1.02,55.16 1.68,55.16 2.54,55.52 2.9,56.38 2.9,56.83 2.85,57.18 2.7,57.5 1.02,57.5 1.02,61.53 5.11,61.53 5.61,61.03 5.61,56.58 5.38,56.35 5.38,49.04
USB1_SHIELD on L03_SIG1: 1.02,49.37 1.02,50.41 1.68,50.41 2.54,50.77 2.9,51.63 2.9,52.08 2.54,52.94 1.68,53.29 1.02,53.29 1.02,55.16 1.68,55.16 2.54,55.52 2.9,56.38 2.9,56.83 2.54,57.69 1.68,58.04 1.02,58.04 1.02,59.15 5.51,59.15 5.51,49.37
VMAIN on TOP: 163.85,76.1 166.11,76.1 166.11,71.95 155.66,71.95 155.66,76.42 158.55,76.42 158.55,83.78 163.85,83.78
VMAIN on TOP: 155.4,61.98 155.4,63 155.27,63.12 153.85,63.12 153.85,62.53 153.82,62.53 152.17,60.88 152.17,58.27 152.27,58.17 153.95,58.17 154.36,58.57 154.36,59.74 154.76,60.15 154.76,61.34
VMAIN on TOP: 148.72,88.41 148.72,93.34 149.63,93.34 151.78,91.19 164.69,91.19 164.69,93.07 165.13,93.5 167.54,93.5 167.54,96.47 173.39,96.47 173.39,88.49 173.31,88.41
VMAIN on BOTTOM: 6.99,38.88 11.43,38.88 11.68,38.62 11.68,26.94 11.43,26.68 6.35,26.68 6.35,38.24
VMAIN on BOTTOM: 57.91,22.37 57.91,23.64 57.44,24.11 57.18,24.11 56.77,24.53 56.77,27.59 58.29,27.59 58.29,22.49 58.17,22.37
VMAIN on L03_SIG1: 151.64,51.96 151.64,79.64 158.75,86.76 170.05,86.76 172.21,84.6 172.21,81.04 173.35,79.9 173.35,49.8 171.83,48.27 155.32,48.27
VMAIN on L06_PWR2: 164.85,97.41 176.78,97.41 176.78,9.16 9.02,9.16 1.52,16.66 1.52,39.11 14.37,39.11 14.37,26.72 22.34,26.72 30.38,18.68 49.15,18.68 51.82,21.35 51.82,26.58 53.7,28.46 63.37,28.46 63.37,21.39 66.71,18.05 147.07,18.05 164.85,35.83
VPP_1V8 on BOTTOM: 138.81,106.19 138.81,102.38 141.35,102.38 142.37,103.39 142.37,106.19
VPP_DDR_2V5 on BOTTOM: 82.85,108.47 82.85,111.15 80.69,111.15 80.69,108.47
VPP_DDR_2V5 on BOTTOM: 90.42,128.09 91.82,128.09 91.82,125.36 92.53,124.66 92.53,123.01 90.42,123.01
XDS_SHIELD on TOP: 172.85,18.68 172.85,21.99 174.75,21.99 174.75,25.29 174.62,25.41 171.04,25.41 171.04,29.22 177.46,29.22 177.46,18.68
XDS_USB_VBUS on TOP: 167.26,11.78 167.26,13.81 164.2,13.81 164.2,12.86 165.28,11.78
XDS_USB_VBUS on L03_SIG1: 142.62,33.42 142.62,30.24 144.02,28.84 161.42,28.84 164.19,26.07 164.19,12.48 166.12,10.56 171.96,10.56 173.1,11.7 173.1,27.57 166.37,34.3 143.51,34.3
N17786037 on TOP: 32.69,115.33 32.69,121.27 39.75,121.27 39.75,118.51 33.53,118.51 33.02,118 33.02,115.33 33.02,115.33
N17839730 on TOP: 5.89,45.81 5.89,41.32 14.33,41.32 14.33,45.81
N18546005 on TOP: 166.75,105.18 171.08,105.18 172.31,103.94 172.31,96.82 167.34,96.82 167.13,96.62 167.13,94.13 166.98,93.98 164.82,93.98 164.44,94.36 164.44,96.29 164.08,96.65 162.05,96.65 162.05,100.48
N18546005 on L08_SIG2: 166.75,105.18 171.08,105.18 172.31,103.94 172.31,96.82 167.34,96.82 167.13,96.62 167.13,94.13 166.98,93.98 164.82,93.98 164.74,94.06 164.74,95.99 163.86,96.88 162.05,96.88 162.05,100.48
N18968753 on TOP: 33.96,52.59 28.27,52.59 28.02,52.85 28.02,54.88 28.14,55.01 33.96,55.01
N19753729 on TOP: 167.58,80.5 171.13,80.5 171.13,64.78 167.77,64.78 167.77,68.14 166.33,69.57 166.33,74.52 167.58,74.52
N19753760 on TOP: 176.76,78.55 176.76,69.64 173.64,69.64 173.3,69.98 173.3,76.85 173.56,77.11 173.56,78.55
N19754201 on TOP: 151.81,64.15 150.37,65.59 150.37,71.37 151.19,72.2 151.19,76.76 151.63,77.2 151.63,80.56 154.23,80.56 154.23,77.54 154.95,76.81 154.95,71.26 156.03,70.18 156.03,64.15
N19754522 on TOP: 140.13,76.02 146.11,76.02 147.74,74.4 147.74,64.73 140.13,64.73
N26004036 on TOP: 149.95,93.53 151.71,91.76 157.46,91.76 157.46,94.49 149.9,94.49 149.9,93.53
N26016842 on BOTTOM: 57.77,21.1 58.29,21.1 58.29,13.73 56.36,13.73 56.36,18.25 57.77,19.66
N26733205 on TOP: 19.38,61.23 19.38,55.29 12.32,55.29 12.32,59.28 12.34,59.3 16.76,59.3 17.77,58.3 18.78,58.3 19.05,58.56 19.05,61.23 19.05,61.23
N26735457 on TOP: 98.81,119.29 92.96,119.29 92.96,126.35 95.89,126.35 95.89,119.87 96.14,119.62 98.8,119.62 98.81,119.62
N26735496 on BOTTOM: 134.22,122.17 134.22,118.76 140.76,118.76 140.76,122.17
N26736579 on TOP: 124.36,73.08 124.36,76.74 130.71,76.74 130.71,73.08

Small or netless copper shapes (teardrops, artwork), in the pictures only: 1376 on TOP, 1156 on BOTTOM, 383 on L03_SIG1, 11 on L05_PWR1, 7 on L06_PWR2, 329 on L08_SIG2

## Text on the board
Ref Des/Assembly Bottom: A | PROC101A ASSEMBLY BOTTOM REV A
Ref Des/Silkscreen Bottom: PCIE RST SEL | A | PCIE PRSNT SEL | FOR EVALUATION ONLY; | NOT FCC APPROVED FOR RESALE
User.Comments: BOARD NAME: | AM64x EVM  BOARD | REV: B | DATE: 01/03/21 | DESCRIPTION: | SHEET | OF | 17 | PROC101E2 | SCALE: 1 | TEXAS INSTRUMENTS
Ref Des/Assembly Top: PROC101A ASSEMBLY TOP REV B
Ref Des/Silkscreen Top: FSI | MCAN1 | CPSW PHY | HSE | BOOTMODE 0-7 | GND | JTAG MUX SEL | VDD CORE | BOOTMODE 8-15 | I2C0 | VDDR CORE | ADC | MCU RST | SOC WARM RST | I2C1 | MCU RSTSTATz | UART | JTAG | OFF | ON | A | MCAN0 | ICSSG PHY | LATCH IN1 | SYNC OUT2 | LATCH IN0 | SYNC OUT0 | SOC/MCU GPIO | MCU WARM RST | SOC POR RST | RSTSTATz | PORz OUT | SYNC1 OUT | MCU PORz | SAFETY | 12V IN | OFF/ON SWITCH | DISPLAY | PCIE | ASSY# | SL# | AM64x/AM243x EVM | PROC101B | OPN# | USB2.0
PAGE_OUTLINE: LAYOUT BY | REVIEWED BY | APPROVED BY | SIGNATURES | AMB | UD | ZA | DATE | 021221 | SCALE: | SIZE | D | NONE | TEXAS INSTRUMENTS | AM64x  EVM  BOARD | SHEET 1 OF 17 | PROC101B | Rev | B
DISPLAY_TOP: 18. | 16. | 17. | FOR STACKUP DETAIL PROC101_STACKUP.PDF SHALL BE REFERRED. | ENSURE UL REGISTERED E-FILE NUMBER SHALL BE PRINTED ON THE PCB SILKSCREEN. | VIA ON PAD SHALL BE RESIN FILLED AND CAP-PLATED. | DETAIL-A
DIMENSION: 32.725 | BACKING PLATE OUTLINE | NON-PLATED MOUNTING HOLE | 30.225 | SOCKET OUTLINE | 4X | dia | 1.70 | 13.8625 | 8.7825 | 8.0000 | 0 | 0.80 | TYP | 441X | 0.42 | MIN  PADS | 11.3225 | NON-PLATED ALIGNMENT HOLE | 2X | 0.850
User.41: 03 | 04 | 01 | 02 | STRIPLINE | MICROSTRIP | EDGE COUPLED STRIPLINE | EDGE COUPLED MICROSTRIP | L3,L8 | L1,L10 | 3.7 | 4.2 | 5.8 | 9.05 | 3.6 | 6 | 4.4 | NA | 90 | 40 | 50 | L2/L4,L7/L9 | L2,L9
User.45: FIGURE | SIZE | 8.0 | 28.0 | 36.0 | 40.0 | 44.0 | 66.0 | 78.0 | 34.0 | 50.0 | 64.0 | 92.0 | 108.0 | 126.0 | 52.0x24.0 | 52.0x26.0 | 64.0x32.0 | 80.0x40.0 | 82.0x34.0 | DRILL CHART: TOP to BOTTOM | ALL UNITS ARE IN MILS | TOLERANCE | +3.0/-3.0 | +2.0/-2.0 | +1.0/-1.0 | PLATED | NON-PLATED | QTY | 3163 | 64 | 38 | 33 | 101 | 18 | 6 | 1 | 2 | 4 | 13 | 6 - Provide serial numbers to the assembled boards for identification. | 7 - The assembled board are wrapped in ESD Covers(individual) and packed securely before shipment. | ASSEMBLY NOTES:- | 1 - All MSL components should be baked as per JEDEC standard. | 2 - PCB should be baked at 120 degree for 8 hours. | 3 - Board assembly must comply with workmanship standards IPC-A-610 Class 2, unless otherwise specified. | 4 - These assemblies are ESD sensitive, ESD precautions shall be observed. | 5 - These assemblies must be clean and free from flux and all contaminants. Use of no clean flux is not acceptable. | PROC101 E2 ASSEMBLY TOP | PROC101 E2 ASSEMBLY BOTTOM
